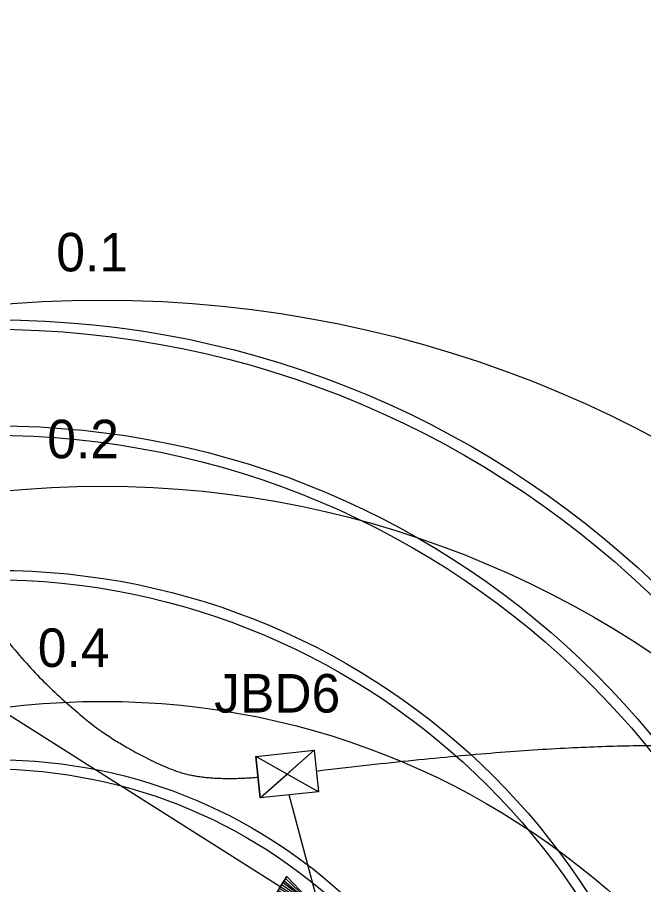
# Model space of a CAD drawing. Extents: x 1638506 to 1658005, y 834807 to 846788.
# Drawn here: x 1641025.5 to 1641220.4, y 842698.3 to 842968.5 of the extents above; entities that cross this region are included whole.
import ezdxf

# ---------------------------------------------------------------- set-up
doc = ezdxf.new("R2010")
doc.units = 0
for name, color, linetype in [('Default', 7, 'Continuous'), ('Old_Level_1', 7, 'Continuous'), ('Old_Level_4', 7, 'Continuous'), ('Scratch_Level_0', 7, 'Continuous')]:
    doc.layers.add(name, color=color, linetype=linetype)

msp = doc.modelspace()

# ---------------------------------------------------------------- linework, layer by layer
at = {"layer": 'Default'}
for p, q in [((1640714.3, 842946.43), (1641119.83, 842689.85)), ((1641119.18, 842727.3), (1641099.63, 842738.26)), ((1641117.81, 842740.19), (1641100.99, 842725.38)), ((1641132.18, 842643.62), (1641110.09, 842726.34)), ((1641124.25, 842673.32), (1641111.22, 842722.11))]:
    msp.add_line(p, q, dxfattribs=at)
for points in [[(1641119.18, 842727.3), (1641100.99, 842725.38), (1641099.63, 842738.26), (1641117.81, 842740.19)], [(1641109.4, 842732.78), (1641099.63, 842738.26), (1641100.99, 842725.38)], [(1641109.4, 842732.78), (1641117.81, 842740.19), (1641119.18, 842727.3)]]:
    msp.add_lwpolyline(points, close=True, dxfattribs=at)
msp.add_lwpolyline([(1641107.33, 842697.76), (1641107.72, 842698.39), (1641119.83, 842689.85), (1641108.09, 842698.97), (1641108.49, 842699.59), (1641119.83, 842689.85), (1641108.88, 842700.22), (1641109.28, 842700.85), (1641119.83, 842689.85), (1641105.39, 842694.61), (1641105.75, 842695.26), (1641119.83, 842689.85), (1641106.18, 842695.86), (1641106.54, 842696.51), (1641119.83, 842689.85), (1641106.93, 842697.14), (1641109.28, 842700.85), (1641105.39, 842694.61), (1641119.83, 842689.85), (1641109.28, 842700.85)], dxfattribs=at)
for points in [[(1640886.69, 842968.5), (1640897.24, 842954.72), (1640925.4, 842917.63), (1640940.05, 842897.05), (1641010.95, 842786.59), (1641043.17, 842750.84), (1641071.53, 842733.99), (1641088.02, 842730.82), (1641100.31, 842731.82)], [(1641118.5, 842733.75), (1641184.14, 842741.69), (1641261.51, 842741.69), (1641322.44, 842734.15), (1641359.07, 842723.88), (1641404.28, 842711.67)]]:
    msp.add_open_spline(points, degree=2, dxfattribs=at)
at = {"layer": 'Old_Level_1'}
for radius in [297, 264, 219, 160]:
    msp.add_circle((1641016.92, 842574.38), radius, dxfattribs=at)
at = {"layer": 'Old_Level_4'}
for centre, radius in [((1641051.91, 842515.45), 365), ((1641538.84, 842469.72), 365), ((1641051.91, 842515.45), 307), ((1641051.91, 842515.45), 240)]:
    msp.add_circle(centre, radius, dxfattribs=at)
at = {"layer": 'Scratch_Level_0'}
for radius in [297, 264, 219, 160]:
    msp.add_circle((1641018.82, 842577.25), radius, dxfattribs=at)

# ---------------------------------------------------------------- texts
at = {"layer": 'Default'}
msp.add_text('JBD6', height=12, dxfattribs=at).set_placement((1641086.71, 842751.96))
at = {"layer": 'Old_Level_4'}
for s, p in [('0.1', (1641037.57, 842889.37)), ('0.2', (1641034.77, 842831.16)), ('0.4', (1641031.82, 842766.15))]:
    msp.add_text(s, height=12, dxfattribs=at).set_placement(p)

doc.saveas('drawing.dxf')
